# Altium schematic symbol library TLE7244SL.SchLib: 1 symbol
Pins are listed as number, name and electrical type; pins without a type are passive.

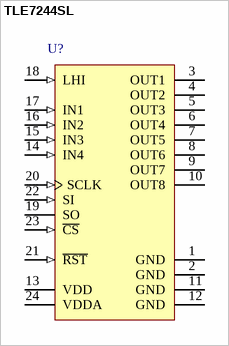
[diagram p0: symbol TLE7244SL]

## TLE7244SL
designator U?
SPIDER-8 Channel Protected Low-Side Relay Switch, 10 uA Quiescent Current, 3 to 5.5 V VDD, -40 to 150 degC, PG-SSOP-24-7, Reel, Green; Manufacturer: Infineon; PartNumber: TLE7244SL; Channels: 8; Cranking mode: FALSE; Daisy-chain capability: TRUE; ID nom: 290 mA; ID(lim) (min): 0.5 A; Open Load Detection: off; Overcurrent limitation or shutdown: No; PWM Inputs: 4; Quiescent Current (max): 10 uA; RDS (on) (max): 1.7 Ohm; RDS (on) (typ): 0.8 Ohm; SPI: 16 Bit; VDD: 3 - 5.5 V; VDS(CL): 41 - 52 V
footprint INF-PG-SSOP-24-7_N (SOP, 24-Leads, Body 8.65x3.9mm, Pitch 0.65mm, IPC Medium Density)
footprint INF-PG-SSOP-24-7_L (SOP, 24-Leads, Body 8.65x3.9mm, Pitch 0.65mm, IPC High Density)
footprint INF-PG-SSOP-24-7_M (SOP, 24-Leads, Body 8.65x3.9mm, Pitch 0.65mm, IPC Low Density)
pins: 1 GND (power) "Ground; common ground for digital, analog and power", 2 GND (power) "Ground; common ground for digital, analog and power", 3 OUT1 (power) "Output Channel 1; Drain of power transistor channel 1", 4 OUT2 (power) "Output Channel 2; Drain of power transistor channel 2", 5 OUT3 (power) "Output Channel 3; Drain of power transistor channel 3", 6 OUT4 (power) "Output Channel 4; Drain of power transistor channel 4", 7 OUT5 (power) "Output Channel 5; Drain of power transistor channel 5", 8 OUT6 (power) "Output Channel 6; Drain of power transistor channel 6", 9 OUT7 (power) "Output Channel 7; Drain of power transistor channel 7", 10 OUT8 (power) "Output Channel 8; Drain of power transistor channel 8", 11 GND (power) "Ground; common ground for digital, analog and power", 12 GND (power) "Ground; common ground for digital, analog and power", 13 VDD (power) "Digital Supply Voltage; Connected to 3.3V or 5V Voltage with Reverse protection Diode and Filter against EMC", 14 IN4 (in) "Control Input; Digital input 3.3 V or 5V. In case of not used keep open.", 15 IN3 (in) "Control Input; Digital input 3.3 V or 5V. In case of not used keep open.", 16 IN2 (in) "Control Input; Digital input 3.3 V or 5V. In case of not used keep open.", 17 IN1 (in) "Control Input; Digital input 3.3 V or 5V. In case of not used keep open.", 18 LHI (in) "Limp Home; Digital input 3.3 V or 5V. In case of not used keep open.", 19 SO (hiz) "Serial data out; Digital output with voltage level referring to VDD .", 20 SCLK (in) "Serial clock; Digital input 3.3 V or 5V.", 21 ~{RST} (in) "Reset input pin; Digital input 3.3 V or 5V. Low active", 22 SI (in) "Serial data in; Digital input 3.3 V or 5V.", 23 ~{CS} (in) "SPI chip select; Digital input 3.3 V or 5V. Low active", 24 VDDA (power) "Analog Supply Voltage; Connected to 5V Voltage with Reverse protection Diode and Filter against EMC"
